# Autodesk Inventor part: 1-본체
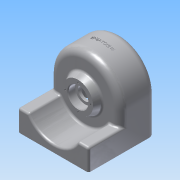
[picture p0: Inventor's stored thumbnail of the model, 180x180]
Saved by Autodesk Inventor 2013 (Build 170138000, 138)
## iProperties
Created: 2015-02
Part Number: 1-본체
Material: 알루미늄 6061
Document SubType Name: Modeling
Designer: Administrator
Density: 2.71 g/cm^3
Mass: 575.526 g
Surface Area: 706.56 cm^2
Volume: 212.371 cm^3
Author: Administrator
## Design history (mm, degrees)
sketch "스케치1"
  geometry: L1 (-50, 25)-(50, 25); L2 (50, 25)-(50, -25); L3 (50, -25)-(-50, -25); L4 (-50, -25)-(-50, 25); L5 (-50, 25)-(50, -25); L6 (50, 25)-(-50, -25); 1 further point
  constraints: 12 end point, 2 midpoint, 2 parallel, 1 horizontal, 1 perpendicular
  dimensions: "d2" = 50 distance of L3.end L1.start; "d4" = 100 distance of L1.start L1.end
extrude "돌출1" new body sketch "스케치1" distance "d5" = 100; taper "d6" = 0 deg
fillet "모깎기1" dims "d7" = 50
fillet "모깎기2" dims "d8" = 10
feature "쉘1" dims "d9" = 4
sketch "스케치2"
  geometry: C1 r 20 at (40, -50); A1 r 40 centre (40, -50) between (0, -50) and (80, -50) reference; 1 further point
  constraints: 1 centre point, 1 coincident
  dimensions: "d10" = 40 diameter of C1
extrude "돌출2" join sketch "스케치2" distance "d12" = 9; taper "d13" = 0 deg
sketch "스케치3"
  geometry: C1 r 25 at (40, 50); A1 r 40 centre (40, 50) between (80, 50) and (0, 50) reference; 1 further point
  constraints: 1 centre point, 1 coincident
  dimensions: "d14" = 50 diameter of C1
extrude "돌출3" join sketch "스케치3" distance "d16" = 10; taper "d17" = -20 deg
node "작업 평면1"
sketch "스케치4"
  geometry: L1 (90, 0)-(80, 0) reference; L2 (80, 0)-(0, 0) reference; L3 (0, 0)-(-10, 0) reference; L4 (-10, 50)-(-10, 0) reference; L5 (-10, 0)-(90, 0); L6 (90, 30)-(74.641, 30); L7 (-10, 0)-(-10, 30); L8 (5.359, 30)-(-10, 30); L9 (90, 0)-(90, 50) reference; L10 (90, 30)-(90, 0); A1 r 40 centre (40, 50) between (5.359, 30) and (74.641, 30); 2 further points
  constraints: 10 end point, 3 collinear, 2 point on circle, 1 centre point, 1 midpoint, 1 perpendicular, 1 point on line, 1 vertical alignment
  dimensions: "d19" = 80 diameter of A1; "d21" = 50 distance of point (40, 0) A1.centre; "d22" = 30 distance between parallel lines of L6 L1
extrude "돌출4" join sketch "스케치4" stored distance "d23" = 10; taper "d24" = 0 deg
sketch "스케치5"
  geometry: L1 (-40, 0)-(-40, -50) reference; L2 (40, -50)-(-40, -50) reference; L3 (40, -50)-(40, 0) reference; A1 r 40 centre (0, 0) between (40, 0) and (-40, 0) reference; 1 further point
hole "구멍1" diameter "d27" = 20; stored, may be unused: countersink angle "d31" = 90 deg, drill point angle "d33" = 0 deg; dims "d25" = 10, "d26" = 10, "d28" = 6, "d29" = 28, "d30" = 8, "d32" = 10
hole "구멍2" diameter "d36" = 20; stored, may be unused: countersink angle "d40" = 90 deg, drill point angle "d42" = 0 deg; dims "d34" = 10, "d35" = 10, "d37" = 6, "d38" = 28, "d39" = 10, "d41" = 10
sketch "스케치6"
  geometry: C1 r 14 at (0, 0) reference; C2 r 21.36 at (0, 0) reference; A1 r 18 centre (0, 0) between (0, 18) and (0, -18); 3 further points
  constraints: 4 point on circle, 2 horizontal alignment, 2 vertical alignment, 1 centre point, 1 coincident
  dimensions: "d43" = 36 diameter of A1
hole "구멍3" sketch "스케치6" at (0, 18), (0, -18), (18, 0), (-18, 0) diameter "d45" = 2.459; stored, may be unused: countersink angle "d49" = 90 deg, drill point angle "d51" = 118 deg; dims "d46" = 6, "d47" = 28, "d48" = 10, "d50" = 9
sketch "스케치7"
  geometry: L1 (-40, 21)-(40, 21) reference; L2 (50, -70)-(-50, -70) reference; L3 (-41.75, -28)-(41.75, -28); L4 (41.75, -28)-(41.75, -61); L5 (41.75, -61)-(-41.75, -61); L6 (-41.75, -61)-(-41.75, -28); L7 (-41.75, -28)-(41.75, -61); L8 (41.75, -28)-(-41.75, -61); 9 further points
  constraints: 12 end point, 5 coincident, 4 midpoint, 2 parallel, 1 horizontal, 1 perpendicular, 1 vertical alignment
  dimensions: "d52" = 83.5 distance of L4.end L5.end; "d54" = 33 distance of L3.end L4.end; "d56" = 9 distance between parallel lines of L2 L5
hole "구멍4" sketch "스케치7" at (-41.75, -61), (-41.75, -28), (41.75, -28), (41.75, -61) diameter "d57" = 5.134; stored, may be unused: countersink angle "d61" = 90 deg, drill point angle "d63" = 118 deg; dims "d58" = 10, "d59" = 28, "d60" = 10, "d62" = 13
fillet "모깎기3" dims "d64" = 0.3
fillet "모깎기4" dims "d65" = 3
fillet "모깎기5" dims "d66" = 3
node "작업 평면2"
sketch "스케치8"
  geometry: L1 (-40, 37.5)-(40, 37.5) reference; 3 further points
  constraints: 1 midpoint, 1 vertical alignment, 1 other
  dimensions: "d67" = 25 distance from line of point (0, 12.5) L1
feature "엠보싱1" sketch "스케치8" dims "d2" = 50, "d4" = 100, "d68" = 0.5, "d69" = 0
chamfer "모따기1" distance "d70" = 1; stored, may be unused: second distance "d71" = 2, angle "d72" = 45 deg
node "솔리드1"
other parameters: "d18" = -95
